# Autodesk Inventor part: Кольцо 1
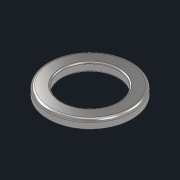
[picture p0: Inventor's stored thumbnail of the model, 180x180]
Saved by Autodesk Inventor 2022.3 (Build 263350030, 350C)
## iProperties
Created: 2022-08
Part Number: Кольцо 1
Material: Сталь 40ХНМА
Document SubType Name: Modeling
Designer: Карташов
Density: 7.85 g/cm^3
Appearance: С умеренной полировкой
Author: Карташов
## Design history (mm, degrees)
sketch "Эскиз1"
  geometry: L1 (0, 0)-(0, 9.446); L2 (40, 1.5)-(40, 10); L3 (42, 12)-(56, 12); L4 (60, 8)-(60, 0); L5 (60, 0)-(55, 0); L6 (55, 0)-(55, 5.5); L7 (53.5, 7)-(46.5, 7); L8 (45, 5.5)-(45, 1.5); L9 (43.5, 0)-(41.5, 0); A1 r 4 centre (56, 8) between (60, 8) and (56, 12); A2 r 2 centre (42, 10) between (42, 12) and (40, 10); A3 r 1.5 centre (41.5, 1.5) between (40, 1.5) and (41.5, 0); A4 r 1.5 centre (43.5, 1.5) between (43.5, 0) and (45, 1.5); A5 r 1.5 centre (46.5, 5.5) between (46.5, 7) and (45, 5.5); A6 r 1.5 centre (53.5, 5.5) between (55, 5.5) and (53.5, 7); 5 further points
  constraints: 18 end point, 12 point on circle, 12 tangent, 8 point on line, 6 centre point, 5 vertical, 3 equal radius, 2 horizontal, 2 horizontal alignment, 2 perpendicular, 1 midpoint
  dimensions: "d0" = 120 diameter of L4 point (0, 4.723); "d1" = 80 diameter of L2 L1; "d2" = 110 diameter of L6 L1; "d3" = 90 diameter of L8 L1; "d4" = 7 distance of L5.end point (55, 7); "d5" = 12 distance of point (60, 12) L4.end; "d6" = 4 radius of A1; "d7" = 2 radius of A2; "d8" = 1.5 radius of A3
revolve "Вращение1" sketch "Эскиз1" stored, may be unused: angle "d9" = 90 deg
node "Твердое тело1"
